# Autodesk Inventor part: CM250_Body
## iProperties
Author: ovrein
Created: 2001-03
Part Number: CM250_Body
Material: S355J2G3
Document SubType Name: Modeling
Designer: ovrein
Control State: 0
Master: False
Checked Out: False
Last Check In Date: 2001-07-27
PropertySet Name: Design Tracking Control
Last Check In By: ovrein
Shininess: 41.0
PropertySet Name: _Private Model Information
Density: 0.0
Volumn: 0.0
Area: 0.0
PropertySet Name: Model Information
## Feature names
1. Extrusion1
2. rod hole [Extrusion]
3. Extrusion3
4. Extrusion4
5. Fillet1
6. Chamfer1
7. Extrusion5
8. Revolution1
9. Extrusion7
10. Extrusion8
11. Revolution2
12. Fillet3
